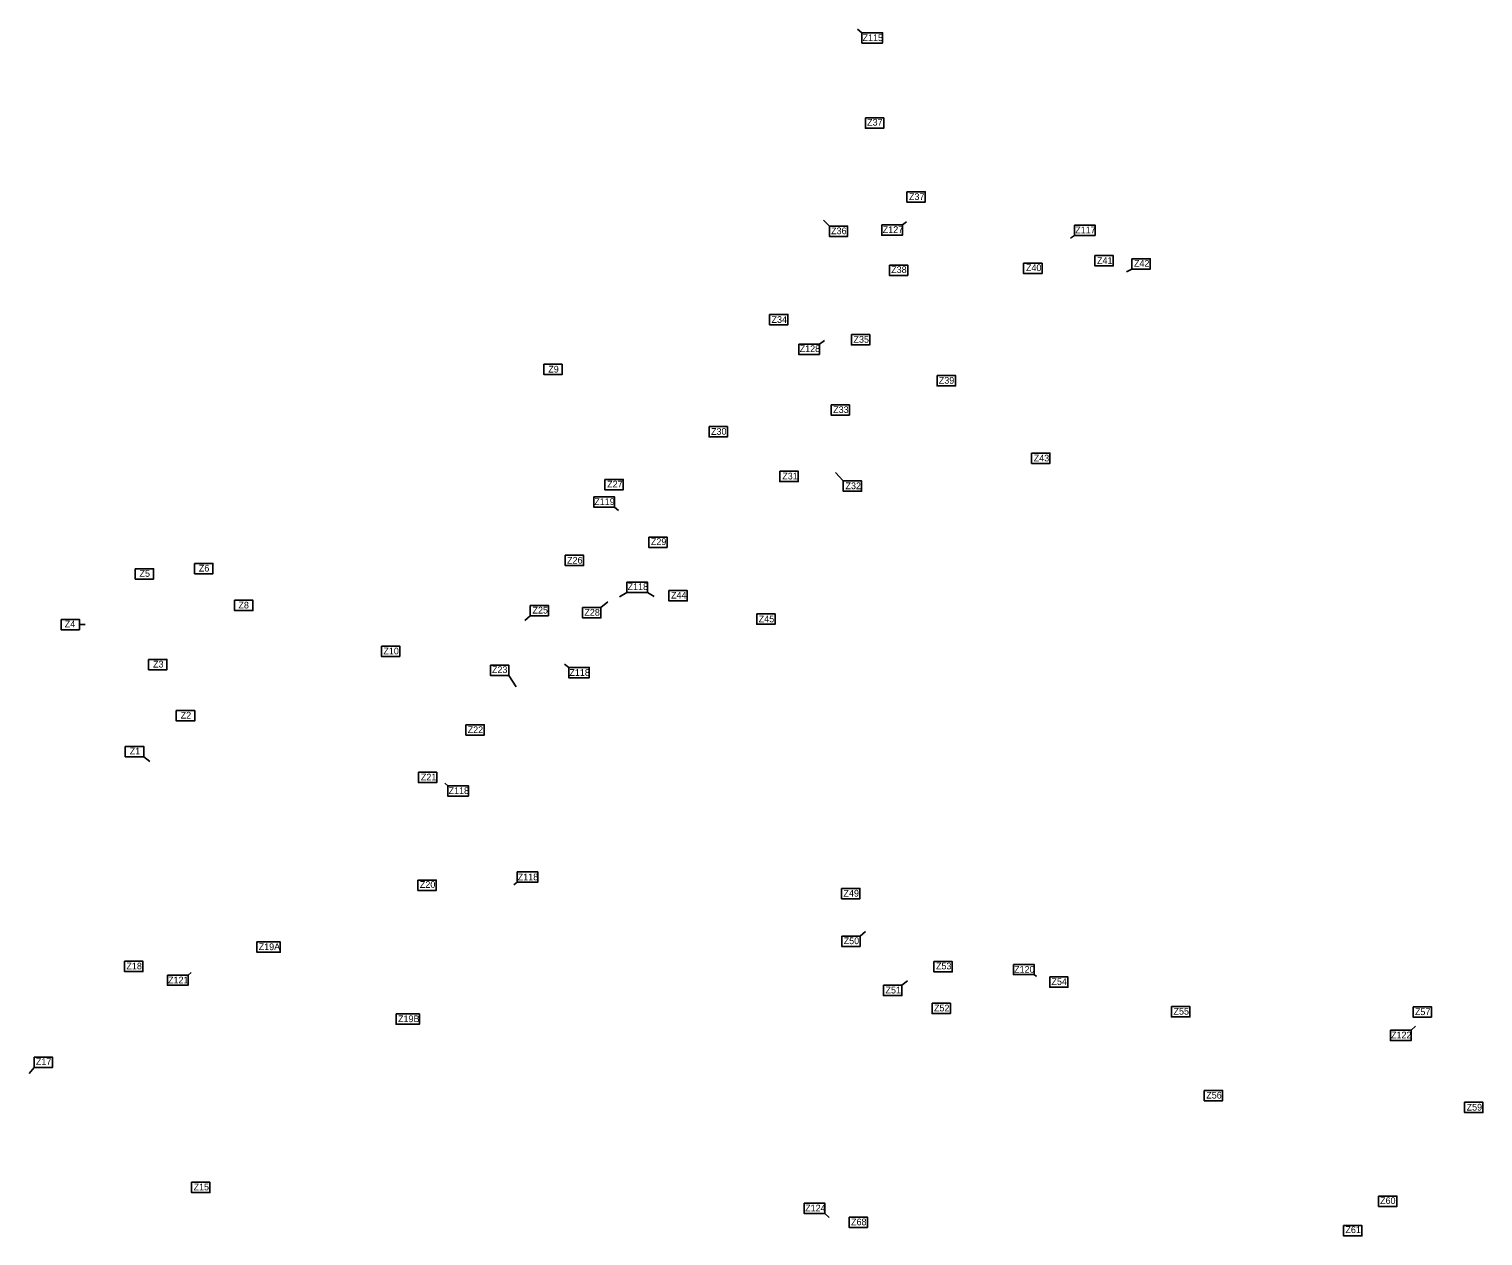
# Model space of a CAD drawing. Extents: x -443483 to -438119, y -1133472 to -1129797.
# Drawn here: x -443022 to -440855, y -1131596 to -1129797 of the extents above; entities that cross this region are included whole.
import ezdxf

# ---------------------------------------------------------------- set-up
doc = ezdxf.new("R2010")
doc.units = 0
doc.layers.add('Vrstva 3', color=7, linetype='Continuous')
doc.layers.add('Vrstva 8', color=7, linetype='Continuous')

msp = doc.modelspace()

# ---------------------------------------------------------------- linework, layer by layer
at = {"layer": 'Vrstva 3'}
for p, q in [((-441780.6, -1129802.1), (-441787.2, -1129796.7)), ((-441829.1, -1130090.3), (-441838, -1130081.7)), ((-441378.1, -1130154.6), (-441386.2, -1130158.4)), ((-441808.5, -1130470.4), (-441819.7, -1130457.7)), ((-442169.8, -1130659.1), (-442159.4, -1130650.4)), ((-442947.3, -1130684.5), (-442938.5, -1130684.6)), ((-442275.3, -1130671.3), (-442283.1, -1130678.3)), ((-442307.2, -1130760.3), (-442296.3, -1130777.1)), ((-442851.5, -1130881.4), (-442842.3, -1130888.4)), ((-441783.2, -1131148.9), (-441775.1, -1131141.9)), ((-441721, -1131222.3), (-441712.8, -1131215.4)), ((-443014.7, -1131344.8), (-443022.4, -1131353.5))]:
    msp.add_line(p, q, dxfattribs=at)
for points in [[(-441780.6, -1129802.1), (-441749.8, -1129802.1), (-441749.8, -1129817.5), (-441780.6, -1129817.5)], [(-441775.4, -1129929), (-441748, -1129929), (-441748, -1129944.4), (-441775.4, -1129944.4)], [(-441713.5, -1130039.3), (-441686.2, -1130039.3), (-441686.2, -1130054.7), (-441713.5, -1130054.7)], [(-441829.1, -1130090.3), (-441801.8, -1130090.3), (-441801.8, -1130105.7), (-441829.1, -1130105.7)], [(-441539.4, -1130145.7), (-441512, -1130145.7), (-441512, -1130161.1), (-441539.4, -1130161.1)], [(-441433.1, -1130134.4), (-441405.7, -1130134.4), (-441405.7, -1130149.8), (-441433.1, -1130149.8)], [(-441378.1, -1130139.2), (-441350.7, -1130139.2), (-441350.7, -1130154.6), (-441378.1, -1130154.6)], [(-441739.6, -1130148.5), (-441712.2, -1130148.5), (-441712.2, -1130163.9), (-441739.6, -1130163.9)], [(-441918.2, -1130222.1), (-441890.9, -1130222.1), (-441890.9, -1130237.5), (-441918.2, -1130237.5)], [(-441796.3, -1130252.1), (-441768.9, -1130252.1), (-441768.9, -1130267.5), (-441796.3, -1130267.5)], [(-442254.8, -1130296.3), (-442227.5, -1130296.3), (-442227.5, -1130311.7), (-442254.8, -1130311.7)], [(-441668.4, -1130313.2), (-441641, -1130313.2), (-441641, -1130328.6), (-441668.4, -1130328.6)], [(-441826.6, -1130356.8), (-441799.2, -1130356.8), (-441799.2, -1130372.2), (-441826.6, -1130372.2)], [(-442008.5, -1130389.3), (-441981.2, -1130389.3), (-441981.2, -1130404.7), (-442008.5, -1130404.7)], [(-441527.5, -1130428.9), (-441500.2, -1130428.9), (-441500.2, -1130444.3), (-441527.5, -1130444.3)], [(-442163.9, -1130468.1), (-442136.5, -1130468.1), (-442136.5, -1130483.5), (-442163.9, -1130483.5)], [(-441903, -1130455.8), (-441875.6, -1130455.8), (-441875.6, -1130471.2), (-441903, -1130471.2)], [(-441808.5, -1130470.4), (-441781.1, -1130470.4), (-441781.1, -1130485.8), (-441808.5, -1130485.8)], [(-442098.4, -1130554.1), (-442071.1, -1130554.1), (-442071.1, -1130569.5), (-442098.4, -1130569.5)], [(-442864.1, -1130601.3), (-442836.8, -1130601.3), (-442836.8, -1130616.7), (-442864.1, -1130616.7)], [(-442775.7, -1130593.4), (-442748.3, -1130593.4), (-442748.3, -1130608.8), (-442775.7, -1130608.8)], [(-442222.8, -1130581.2), (-442195.5, -1130581.2), (-442195.5, -1130596.5), (-442222.8, -1130596.5)], [(-442068.4, -1130633.9), (-442041.1, -1130633.9), (-442041.1, -1130649.3), (-442068.4, -1130649.3)], [(-442715.9, -1130648.2), (-442688.5, -1130648.2), (-442688.5, -1130663.6), (-442715.9, -1130663.6)], [(-442275.3, -1130655.9), (-442247.9, -1130655.9), (-442247.9, -1130671.3), (-442275.3, -1130671.3)], [(-442197.1, -1130659.1), (-442169.8, -1130659.1), (-442169.8, -1130674.5), (-442197.1, -1130674.5)], [(-442974.7, -1130676.8), (-442947.3, -1130676.8), (-442947.3, -1130692.2), (-442974.7, -1130692.2)], [(-441937.3, -1130668.5), (-441909.9, -1130668.5), (-441909.9, -1130683.9), (-441937.3, -1130683.9)], [(-442497.1, -1130716.5), (-442469.7, -1130716.5), (-442469.7, -1130731.9), (-442497.1, -1130731.9)], [(-442844.2, -1130736.3), (-442816.9, -1130736.3), (-442816.9, -1130751.7), (-442844.2, -1130751.7)], [(-442334.6, -1130744.9), (-442307.2, -1130744.9), (-442307.2, -1130760.3), (-442334.6, -1130760.3)], [(-442802.8, -1130812.7), (-442775.4, -1130812.7), (-442775.4, -1130828.1), (-442802.8, -1130828.1)], [(-442370.9, -1130833.9), (-442343.6, -1130833.9), (-442343.6, -1130849.2), (-442370.9, -1130849.2)], [(-442878.9, -1130866.1), (-442851.5, -1130866.1), (-442851.5, -1130881.4), (-442878.9, -1130881.4)], [(-442441.8, -1130904.7), (-442414.5, -1130904.7), (-442414.5, -1130920.1), (-442441.8, -1130920.1)], [(-442442.5, -1131065.5), (-442415.2, -1131065.5), (-442415.2, -1131080.9), (-442442.5, -1131080.9)], [(-441810.9, -1131077.7), (-441783.5, -1131077.7), (-441783.5, -1131093.1), (-441810.9, -1131093.1)], [(-442682.6, -1131157.6), (-442647.9, -1131157.6), (-442647.9, -1131173), (-442682.6, -1131173)], [(-441810.6, -1131148.9), (-441783.2, -1131148.9), (-441783.2, -1131164.3), (-441810.6, -1131164.3)], [(-442879.9, -1131186.4), (-442852.5, -1131186.4), (-442852.5, -1131201.8), (-442879.9, -1131201.8)], [(-441673.2, -1131186.9), (-441645.8, -1131186.9), (-441645.8, -1131202.2), (-441673.2, -1131202.2)], [(-441748.4, -1131222.3), (-441721, -1131222.3), (-441721, -1131237.7), (-441748.4, -1131237.7)], [(-441500.6, -1131209.7), (-441473.3, -1131209.7), (-441473.3, -1131225.1), (-441500.6, -1131225.1)], [(-441676, -1131249.1), (-441648.6, -1131249.1), (-441648.6, -1131264.5), (-441676, -1131264.5)], [(-442475.1, -1131264.8), (-442440.3, -1131264.8), (-442440.3, -1131280.2), (-442475.1, -1131280.2)], [(-441319, -1131254), (-441291.6, -1131254), (-441291.6, -1131269.4), (-441319, -1131269.4)], [(-440958.8, -1131254.3), (-440931.4, -1131254.3), (-440931.4, -1131269.7), (-440958.8, -1131269.7)], [(-443014.7, -1131329.4), (-442987.3, -1131329.4), (-442987.3, -1131344.8), (-443014.7, -1131344.8)], [(-441270.2, -1131379), (-441242.8, -1131379), (-441242.8, -1131394.4), (-441270.2, -1131394.4)], [(-440882, -1131396.5), (-440854.6, -1131396.5), (-440854.6, -1131411.9), (-440882, -1131411.9)], [(-442780, -1131515.9), (-442752.6, -1131515.9), (-442752.6, -1131531.3), (-442780, -1131531.3)], [(-441010.2, -1131536.4), (-440982.9, -1131536.4), (-440982.9, -1131551.8), (-441010.2, -1131551.8)], [(-441799.8, -1131567.7), (-441772.4, -1131567.7), (-441772.4, -1131583.1), (-441799.8, -1131583.1)], [(-441062.3, -1131580.5), (-441035, -1131580.5), (-441035, -1131595.9), (-441062.3, -1131595.9)]]:
    msp.add_lwpolyline(points, close=True, dxfattribs=at)
at = {"layer": 'Vrstva 8'}
for p, q in [((-441720.1, -1130088.6), (-441714.3, -1130084)), ((-441463.6, -1130104.2), (-441469.4, -1130108.5)), ((-441844, -1130266.2), (-441836.1, -1130260.9)), ((-442149.3, -1130509.6), (-442143.6, -1130514.2)), ((-442131, -1130636.5), (-442142.2, -1130643.1)), ((-442100.3, -1130636.5), (-442090.5, -1130642.7)), ((-442217.8, -1130748.4), (-442224.2, -1130743.6)), ((-442398, -1130924.7), (-442402.3, -1130921.1)), ((-442294.8, -1131068.6), (-442299.8, -1131072.4)), ((-442785.3, -1131206.9), (-442780.8, -1131203.4)), ((-441523.9, -1131206.4), (-441520.2, -1131209.2)), ((-440961.7, -1131289.2), (-440954.9, -1131283.1)), ((-441835.8, -1131562.7), (-441829.5, -1131568.4))]:
    msp.add_line(p, q, dxfattribs=at)
for points in [[(-441750.9, -1130088.6), (-441720.1, -1130088.6), (-441720.1, -1130104), (-441750.9, -1130104)], [(-441463.6, -1130088.8), (-441432.8, -1130088.8), (-441432.8, -1130104.2), (-441463.6, -1130104.2)], [(-441463.6, -1130088.8), (-441432.8, -1130088.8), (-441432.8, -1130104.2), (-441463.6, -1130104.2)], [(-441874.8, -1130266.2), (-441844, -1130266.2), (-441844, -1130281.6), (-441874.8, -1130281.6)], [(-442180.1, -1130494.2), (-442149.3, -1130494.2), (-442149.3, -1130509.6), (-442180.1, -1130509.6)], [(-442131, -1130621.1), (-442100.3, -1130621.1), (-442100.3, -1130636.5), (-442131, -1130636.5)], [(-442217.8, -1130748.4), (-442187, -1130748.4), (-442187, -1130763.8), (-442217.8, -1130763.8)], [(-442398, -1130924.7), (-442367.2, -1130924.7), (-442367.2, -1130940.1), (-442398, -1130940.1)], [(-442294.8, -1131053.2), (-442264, -1131053.2), (-442264, -1131068.6), (-442294.8, -1131068.6)], [(-442816.1, -1131206.9), (-442785.3, -1131206.9), (-442785.3, -1131222.3), (-442816.1, -1131222.3)], [(-441554.7, -1131191), (-441523.9, -1131191), (-441523.9, -1131206.4), (-441554.7, -1131206.4)], [(-440992.5, -1131289.2), (-440961.7, -1131289.2), (-440961.7, -1131304.6), (-440992.5, -1131304.6)], [(-441866.6, -1131547.3), (-441835.8, -1131547.3), (-441835.8, -1131562.7), (-441866.6, -1131562.7)]]:
    msp.add_lwpolyline(points, close=True, dxfattribs=at)

# ---------------------------------------------------------------- texts
at = {"layer": 'Vrstva 3'}
for s, p in [('Z115', (-441779.6, -1129814.6)), ('Z37', (-441772.8, -1129940.6)), ('Z37', (-441710.4, -1130051.5)), ('Z36', (-441826.5, -1130102.5)), ('Z41', (-441430, -1130146.8)), ('Z42', (-441374.9, -1130151)), ('Z38', (-441736.9, -1130160.4)), ('Z40', (-441536, -1130157.5)), ('Z34', (-441915.3, -1130234.7)), ('Z35', (-441793.1, -1130264.3)), ('Z9', (-442248.2, -1130308.7)), ('Z39', (-441665.9, -1130325.4)), ('Z33', (-441823.4, -1130369)), ('Z30', (-442005.5, -1130401.6)), ('Z43', (-441524.3, -1130441.2)), ('Z27', (-442160.4, -1130480.1)), ('Z31', (-441899.3, -1130468.1)), ('Z32', (-441805, -1130482.6)), ('Z29', (-442095.2, -1130565.8)), ('Z6', (-442769.2, -1130605.4)), ('Z26', (-442220.1, -1130593.6)), ('Z5', (-442857.7, -1130613.2)), ('Z44', (-442065.1, -1130645.7)), ('Z8', (-442710.2, -1130660.4)), ('Z25', (-442271.7, -1130668)), ('Z28', (-442194.4, -1130671.3)), ('Z4', (-442969.1, -1130688.5)), ('Z45', (-441934.4, -1130681)), ('Z10', (-442494.1, -1130728.9)), ('Z3', (-442837.5, -1130748.5)), ('Z23', (-442332.2, -1130756.7)), ('Z2', (-442796.3, -1130824.6)), ('Z22', (-442368.4, -1130846.3)), ('Z1', (-442872.3, -1130878.1)), ('Z21', (-442438.2, -1130916.8)), ('Z20', (-442439.7, -1131077)), ('Z49', (-441808, -1131090)), ('Z19A', (-442680, -1131169.8)), ('Z50', (-441807.7, -1131160.9)), ('Z18', (-442877.2, -1131198.5)), ('Z53', (-441670.1, -1131198.5)), ('Z51', (-441745.4, -1131234.4)), ('Z54', (-441497.9, -1131221.7)), ('Z52', (-441673.1, -1131261.1)), ('Z19B', (-442472.2, -1131277.2)), ('Z55', (-441315.9, -1131266)), ('Z57', (-440956, -1131266.7)), ('Z17', (-443012.2, -1131341)), ('Z56', (-441267.1, -1131391.1)), ('Z59', (-440878.9, -1131409)), ('Z15', (-442777.1, -1131528)), ('Z60', (-441007.9, -1131548.3)), ('Z68', (-441796.7, -1131580)), ('Z61', (-441059.6, -1131591.7))]:
    msp.add_text(s, height=10, dxfattribs=at).set_placement(p)
at = {"layer": 'Vrstva 8'}
for s, p in [('Z127', (-441749.5, -1130100.6)), ('Z117', (-441462.5, -1130101.2)), ('Z128', (-441873.4, -1130278.2)), ('Z119', (-442179.6, -1130506.2)), ('Z118', (-442129.9, -1130632.9)), ('Z118', (-442216.7, -1130760.9)), ('Z118', (-442396.9, -1130937.1)), ('Z118', (-442293.7, -1131065.7)), ('Z120', (-441553.6, -1131203.5)), ('Z121', (-442815.1, -1131219.3)), ('Z122', (-440991.6, -1131301.3)), ('Z124', (-441865.2, -1131559.3))]:
    msp.add_text(s, height=10, dxfattribs=at).set_placement(p)

doc.saveas('drawing.dxf')
